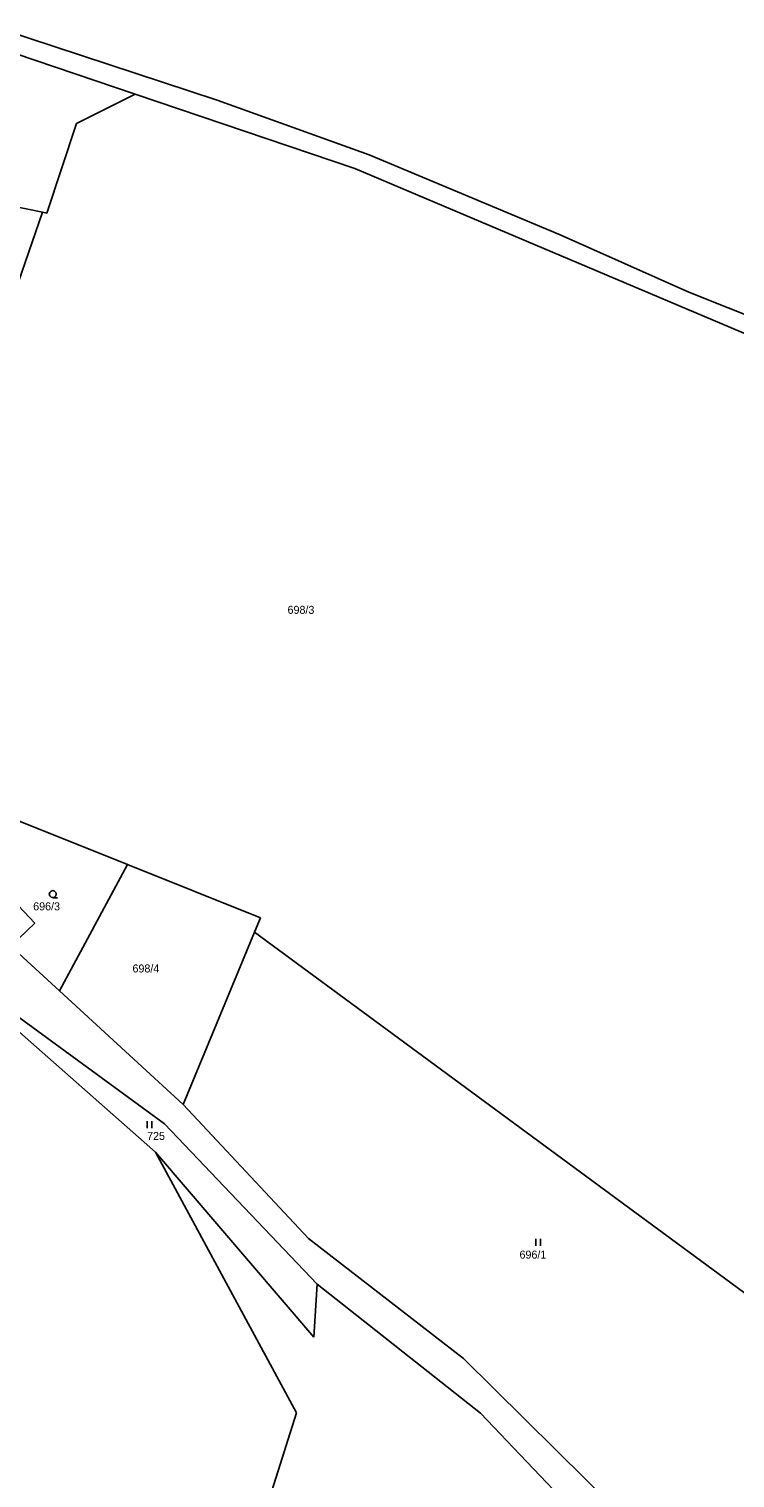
# Model space of a CAD drawing. Extents: x -852001 to -842497, y -1063614 to -1052182.
# Drawn here: x -850483.1 to -850333.2, y -1053768.6 to -1053460.7 of the extents above; entities that cross this region are included whole.
import ezdxf

# ---------------------------------------------------------------- set-up
doc = ezdxf.new("R2010")
doc.units = 0
for name, color, linetype in [('Default', 7, 'Continuous'), ('KN_HRANICE', 7, 'Continuous'), ('KN_KULTURY', 7, 'Continuous'), ('KN_PARCELY', 7, 'Continuous')]:
    doc.layers.add(name, color=color, linetype=linetype)

# ---------------------------------------------------------------- blocks, each defined once
blk = doc.blocks.new('304')
at = {"layer": 'Default'}
blk.add_lwpolyline([(0, 0), (-0.38, 0.1), (-0.65, 0.37), (-0.75, 0.74), (-0.65, 1.11), (-0.38, 1.38), (-0.01, 1.48), (0.36, 1.38), (0.63, 1.11), (0.73, 0.73), (0.63, 0.35), (0.36, 0.08), (-0.02, -0.02), (0.98, -0.02)], dxfattribs=at)
blk = doc.blocks.new('306')
at = {"layer": 'Default'}
for p, q in [((-0.5, 1.5), (-0.5, 0)), ((0.5, 0), (0.5, 1.5))]:
    blk.add_line(p, q, dxfattribs=at)

msp = doc.modelspace()

# ---------------------------------------------------------------- linework, layer by layer
at = {"layer": 'KN_HRANICE'}
for p, q in [((-850489.13, -1053460.73), (-850443.14, -1053475.85)), ((-850486.02, -1053465.93), (-850460.49, -1053474.58)), ((-850461.37, -1053475.02), (-850472.98, -1053480.79)), ((-850460.49, -1053474.58), (-850461.37, -1053475.02)), ((-850460.49, -1053474.58), (-850413.89, -1053490.38)), ((-850443.14, -1053475.85), (-850410.83, -1053487.45)), ((-850472.98, -1053480.79), (-850479.28, -1053499.87)), ((-850410.83, -1053487.45), (-850370.3, -1053504.45)), ((-850317.08, -1053531.39), (-850413.89, -1053490.38)), ((-850480.2, -1053499.68), (-850493.13, -1053497)), ((-850488.23, -1053523.1), (-850480.2, -1053499.68)), ((-850479.28, -1053499.87), (-850480.2, -1053499.68)), ((-850370.3, -1053504.45), (-850343, -1053516.63)), ((-850343, -1053516.63), (-850313.47, -1053528.44)), ((-850501.57, -1053622.5), (-850462.18, -1053638.28)), ((-850462.18, -1053638.28), (-850476.59, -1053665.13)), ((-850462.18, -1053638.28), (-850433.91, -1053649.6)), ((-850486.44, -1053645.86), (-850481.82, -1053650.71)), ((-850486.95, -1053655.61), (-850481.82, -1053650.71)), ((-850433.91, -1053649.6), (-850435.17, -1053652.63)), ((-850435.17, -1053652.63), (-850450.35, -1053689.23)), ((-850435.17, -1053652.63), (-850325.9, -1053733.17)), ((-850456.22, -1053699.36), (-850505.26, -1053656.14)), ((-850505.26, -1053656.14), (-850454.26, -1053693.33)), ((-850476.59, -1053665.13), (-850486.95, -1053655.61)), ((-850450.35, -1053689.23), (-850476.59, -1053665.13)), ((-850423.7, -1053717.72), (-850450.35, -1053689.23)), ((-850454.26, -1053693.33), (-850421.88, -1053727.44)), ((-850426.25, -1053754.8), (-850456.22, -1053699.36)), ((-850456.22, -1053699.36), (-850422.58, -1053738.67)), ((-850390.8, -1053743.21), (-850423.7, -1053717.72)), ((-850421.88, -1053727.44), (-850422.58, -1053738.67)), ((-850387.2, -1053754.86), (-850421.88, -1053727.44)), ((-850345.83, -1053787.76), (-850390.8, -1053743.21)), ((-850431.5, -1053771.32), (-850426.25, -1053754.8)), ((-850347.05, -1053797.05), (-850387.2, -1053754.86))]:
    msp.add_line(p, q, dxfattribs=at)

# ---------------------------------------------------------------- block references
at = {"layer": 'KN_KULTURY'}
for name, p in [('304', (-850478, -1053645.3)), ('306', (-850457.49, -1053694.27)), ('306', (-850375, -1053719.3))]:
    msp.add_blockref(name, p, dxfattribs=at)

# ---------------------------------------------------------------- texts
at = {"layer": 'KN_PARCELY'}
for s, p in [('698/3', (-850428.17, -1053585)), ('696/3', (-850482.17, -1053648)), ('698/4', (-850461.09, -1053661.2)), ('725', (-850457.99, -1053696.78)), ('696/1', (-850378.93, -1053722))]:
    msp.add_text(s, height=1.7, dxfattribs=at).set_placement(p)

doc.saveas('drawing.dxf')
